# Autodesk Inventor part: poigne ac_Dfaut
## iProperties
Created: 2007-07
Part Number: poigne ac_Dfaut
Document SubType Name: Modeling
Designer: EF
Density: 1 g/cm^3
Author: EF
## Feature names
1. Base1
